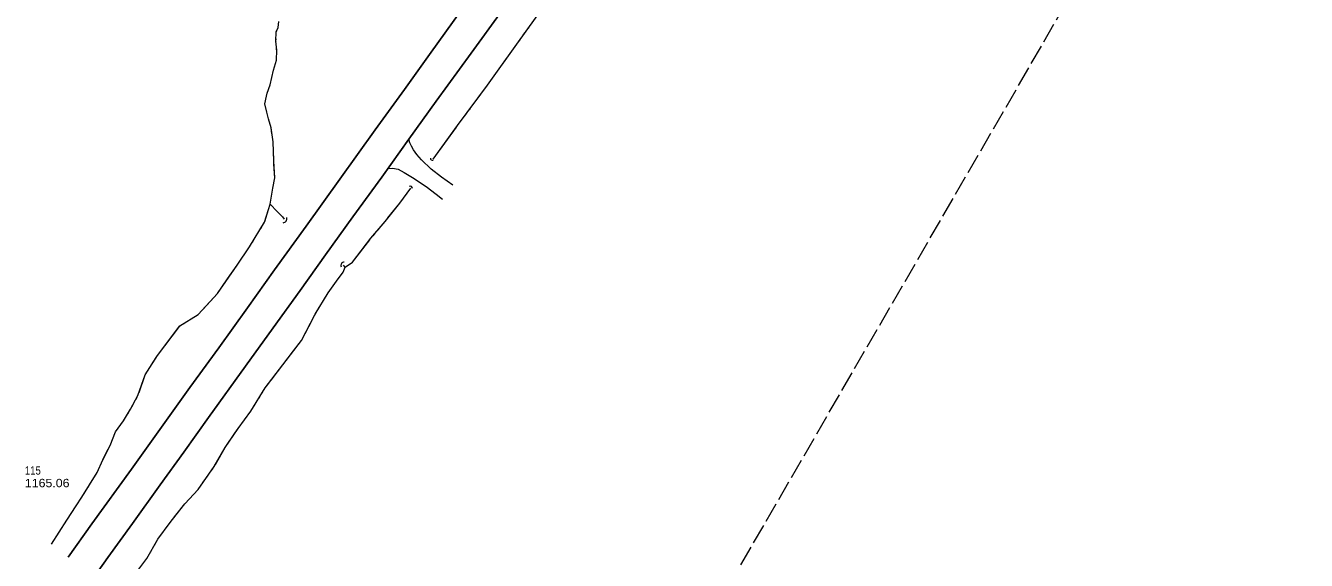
# Model space of a CAD drawing. Extents: x 300582 to 302999, y 51302 to 53600.
# Drawn here: x 301501 to 302416, y 51877 to 52259 of the extents above; entities that cross this region are included whole.
import ezdxf

# ---------------------------------------------------------------- set-up
doc = ezdxf.new("R2010")
doc.units = 0
doc.header["$LTSCALE"] = 2.4
doc.linetypes.add('LONG_DASHED', pattern=[7.5, 6, -1.5])
for name, color, linetype, lineweight in [('11', 7, 'Continuous', 25), ('15', 7, 'Continuous', 13), ('17', 7, 'LONG_DASHED', 13), ('19', 7, 'Continuous', 13), ('4', 7, 'Continuous', 13), ('6', 7, 'Continuous', 13)]:
    doc.layers.add(name, color=color, linetype=linetype, lineweight=lineweight)

msp = doc.modelspace()

# ---------------------------------------------------------------- linework, layer by layer
at = {"layer": '11'}
for points in [[(301548.391, 51863.553), (301559.449, 51878.873), (301576.95, 51903.138), (301596.876, 51930.841), (301613.71, 51954.338), (301631.383, 51978.911), (301657.769, 52015.634), (301677.583, 52043.216), (301696.914, 52069.842), (301715.094, 52095.23), (301734.478, 52122.469), (301755.186, 52150.843), (301774.586, 52177.936), (301794.228, 52205.192), (301819.169, 52239.529), (301841.265, 52270.036)], [(301531.073, 51879.143), (301547.981, 51903.102), (301576.307, 51942.148), (301598.954, 51973.851), (301618.043, 52000.565), (301638.798, 52028.856), (301659.278, 52057.494), (301678.67, 52084.639), (301701.089, 52115.854), (301725.284, 52149.329), (301750.568, 52184.536), (301771.489, 52213.373), (301790.631, 52240.188), (301811.362, 52268.952)]]:
    msp.add_lwpolyline(points, dxfattribs=at)
at = {"layer": '15'}
for centre, radius, start, end in [((301791.565, 52164.414), 1.578, 181.45785, 287.69741), ((301775.456, 52142.567), 1.754, 3.98225, 110.22182), ((301684.611, 52121.072), 2.792, 271.94415, 18.18371), ((301728.508, 52087.63), 2.526, 93.5275, 199.76706)]:
    msp.add_arc(centre, radius, start, end, dxfattribs=at)
at = {"layer": '17'}
for points in [[(301805.935, 52145.158), (301797.947, 52150.805), (301790.514, 52156.607), (301783.582, 52163.243), (301780.306, 52166.934), (301777.897, 52170.282), (301776.435, 52172.9), (301775.342, 52175.242), (301774.655, 52178.032)], [(301759.51, 52156.882), (301763.015, 52157.188), (301767.058, 52156.536), (301771.284, 52154.23), (301777.311, 52150.522), (301786.975, 52144.176), (301794.032, 52138.605), (301798.551, 52135.156)]]:
    msp.add_lwpolyline(points, dxfattribs=at)
at = {"layer": '19'}
for p, q in [((301856.641, 52252.667), (301857.778, 52254.247)), ((301860.054, 52257.408), (301861.192, 52258.988)), ((301680.103, 52241.705), (301679.953, 52243.686)), ((301817.856, 52199.016), (301819.021, 52200.577)), ((301810.871, 52189.651), (301812.035, 52191.212)), ((301814.364, 52194.334), (301815.528, 52195.895)), ((301791.906, 52163.721), (301808.555, 52186.521)), ((301677.85, 52170.04), (301677.789, 52172.025)), ((301678.033, 52164.084), (301677.972, 52166.07)), ((301668.711, 52114.211), (301669.708, 52115.852)), ((301752.622, 52113.204), (301753.805, 52114.614)), ((301756.172, 52117.433), (301757.355, 52118.843)), ((301662.728, 52104.361), (301663.725, 52106.002)), ((301665.719, 52109.286), (301666.717, 52110.927)), ((301749.072, 52108.976), (301750.255, 52110.385)), ((301712.938, 52061.538), (301713.878, 52063.085)), ((301618.673, 52049.324), (301620.311, 52050.327)), ((301710.121, 52056.896), (301711.06, 52058.443)), ((301613.759, 52046.315), (301615.397, 52047.318)), ((301669.874, 51996.976), (301670.818, 51998.52)), ((301672.842, 52001.516), (301673.945, 52002.952)), ((301576.684, 51986.689), (301577.586, 51988.385)), ((301579.39, 51991.775), (301580.292, 51993.47)), ((301667.039, 51992.344), (301667.984, 51993.888)), ((301573.759, 51981.732), (301574.774, 51983.361)), ((301633.35, 51940.911), (301634.398, 51942.387)), ((301627.062, 51932.054), (301628.11, 51933.53)), ((301630.206, 51936.483), (301631.254, 51937.959)), ((301542.496, 51924.689), (301543.511, 51926.317)), ((301539.39, 51919.845), (301540.45, 51921.442)), ((301587.355, 51878.347), (301588.257, 51879.916)), ((301590.061, 51883.055), (301590.963, 51884.625))]:
    msp.add_line(p, q, dxfattribs=at)
for points in [[(301791.906, 52163.721), (301809.482, 52187.79), (301830.94, 52216.555), (301851.723, 52245.836), (301871.798, 52273.721), (301892.388, 52301.74), (301912.128, 52328.766), (301929.268, 52352.195), (301949.377, 52377.856), (301960.301, 52393.412), (301966.147, 52402.343), (301967.688, 52405.372), (301968.679, 52409.012), (301959.948, 52410.257)], [(301675.574, 52131.584), (301677.468, 52142.876), (301678.733, 52150.234), (301678.088, 52162.287), (301677.664, 52176.119), (301676.091, 52186.068), (301674.273, 52192.611), (301673.196, 52197.346), (301671.729, 52203.248), (301673.299, 52210.904), (301675.552, 52216.828), (301677.891, 52227.23), (301679.932, 52234.401), (301680.121, 52241.468), (301679.632, 52247.921), (301679.785, 52254.686), (301681.115, 52257.717), (301681.731, 52262.084)], [(301679.761, 52253.607), (301679.785, 52254.686), (301680.15, 52255.517)], [(301679.653, 52247.648), (301679.632, 52247.921), (301679.671, 52249.634)], [(301837.998, 52226.499), (301851.723, 52245.836), (301854.365, 52249.506)], [(301673.096, 52209.913), (301673.299, 52210.904), (301675.552, 52216.828), (301677.891, 52227.23), (301679.932, 52234.401), (301680.021, 52237.735)], [(301821.349, 52203.698), (301830.94, 52216.555), (301837.998, 52226.499)], [(301676.753, 52181.881), (301676.091, 52186.068), (301674.273, 52192.611), (301673.196, 52197.346), (301671.729, 52203.248), (301673.096, 52209.913)], [(301677.668, 52175.996), (301677.664, 52176.119), (301677.373, 52177.959)], [(301675.574, 52131.584), (301677.468, 52142.876), (301678.733, 52150.234), (301678.204, 52160.115)], [(301729.139, 52086.392), (301734.326, 52090.05), (301747.534, 52107.144), (301757.573, 52119.102), (301768.131, 52132.305), (301775.922, 52142.885)], [(301759.661, 52121.714), (301768.131, 52132.305), (301775.922, 52142.885)], [(301519.094, 51888.425), (301529.994, 51905.669), (301536.786, 51915.922), (301540.824, 51922.006), (301546.373, 51930.91), (301551.813, 51939.819), (301555.823, 51948.75), (301560.971, 51959.062), (301564.923, 51968.729), (301570.545, 51976.577), (301575.725, 51984.886), (301580.95, 51994.707), (301586.21, 52009.576), (301594.814, 52023.362), (301611, 52044.626), (301623.953, 52052.557), (301637.823, 52067.688), (301651.934, 52087.867), (301660.669, 52100.971), (301671.399, 52118.636), (301674.241, 52127.808), (301675.574, 52131.584), (301680.576, 52126.16), (301684.343, 52122.463), (301685.566, 52120.672)], [(301671.572, 52119.194), (301674.241, 52127.808), (301675.574, 52131.584), (301680.576, 52126.16), (301684.343, 52122.463), (301685.566, 52120.672)], [(301729.139, 52086.392), (301734.326, 52090.05), (301746.745, 52106.123)], [(301645.076, 52078.06), (301651.934, 52087.867), (301660.669, 52100.971), (301660.734, 52101.078)], [(301565.774, 51850.43), (301577.273, 51864.821), (301587.227, 51878.124), (301595.197, 51891.992), (301603.924, 51904.078), (301614.514, 51917.254), (301623.912, 51927.618), (301635.554, 51944.015), (301643.255, 51957.553), (301652.479, 51971.137), (301661.697, 51983.613), (301671.907, 52000.299), (301684.429, 52016.598), (301697.839, 52034.033), (301707.662, 52052.845), (301717.008, 52068.242), (301722.828, 52076.581), (301727.636, 52082.995), (301729.139, 52086.392), (301727.991, 52087.925)], [(301715.756, 52066.179), (301717.008, 52068.242), (301722.828, 52076.581), (301727.636, 52082.995), (301729.139, 52086.392), (301727.991, 52087.925)], [(301627.557, 52056.489), (301637.823, 52067.688), (301645.076, 52078.06)], [(301623.588, 52052.333), (301623.953, 52052.557), (301624.961, 52053.657)], [(301707.342, 52052.233), (301707.662, 52052.845), (301708.243, 52053.802)], [(301593.896, 52021.892), (301594.814, 52023.362), (301610.633, 52044.144)], [(301692.147, 52026.632), (301697.839, 52034.033), (301705.667, 52049.024)], [(301676.15, 52005.822), (301684.429, 52016.598), (301692.147, 52026.632)], [(301581.764, 51997.007), (301586.21, 52009.576), (301593.896, 52021.892)], [(301650.164, 51967.728), (301652.479, 51971.137), (301661.697, 51983.613), (301665.15, 51989.256)], [(301558.516, 51954.145), (301560.971, 51959.062), (301564.923, 51968.729), (301570.545, 51976.577), (301571.728, 51978.475)], [(301636.357, 51945.427), (301643.255, 51957.553), (301650.164, 51967.728)], [(301545.541, 51929.575), (301546.373, 51930.91), (301551.813, 51939.819), (301555.823, 51948.75), (301558.516, 51954.145)], [(301607.974, 51909.117), (301614.514, 51917.254), (301623.912, 51927.618), (301624.966, 51929.102)], [(301536.211, 51915.054), (301536.786, 51915.922), (301537.27, 51916.652)], [(301519.094, 51888.425), (301529.994, 51905.669), (301534.093, 51911.856)], [(301592.767, 51887.764), (301595.197, 51891.992), (301603.924, 51904.078), (301607.974, 51909.117)]]:
    msp.add_lwpolyline(points, dxfattribs=at)
at = {"layer": '4', "linetype": 'LONG_DASHED'}
msp.add_line((301858.628, 51609.011), (302416.216, 52571.488), dxfattribs=at)

# ---------------------------------------------------------------- texts
at = {"layer": '6'}
for s, width, p in [('115', 0.85, (301500.128, 51938.166)), ('1165.06', 1.1, (301500.128, 51929.166))]:
    msp.add_text(s, height=6, dxfattribs=dict(at, width=width)).set_placement(p)

doc.saveas('drawing.dxf')
